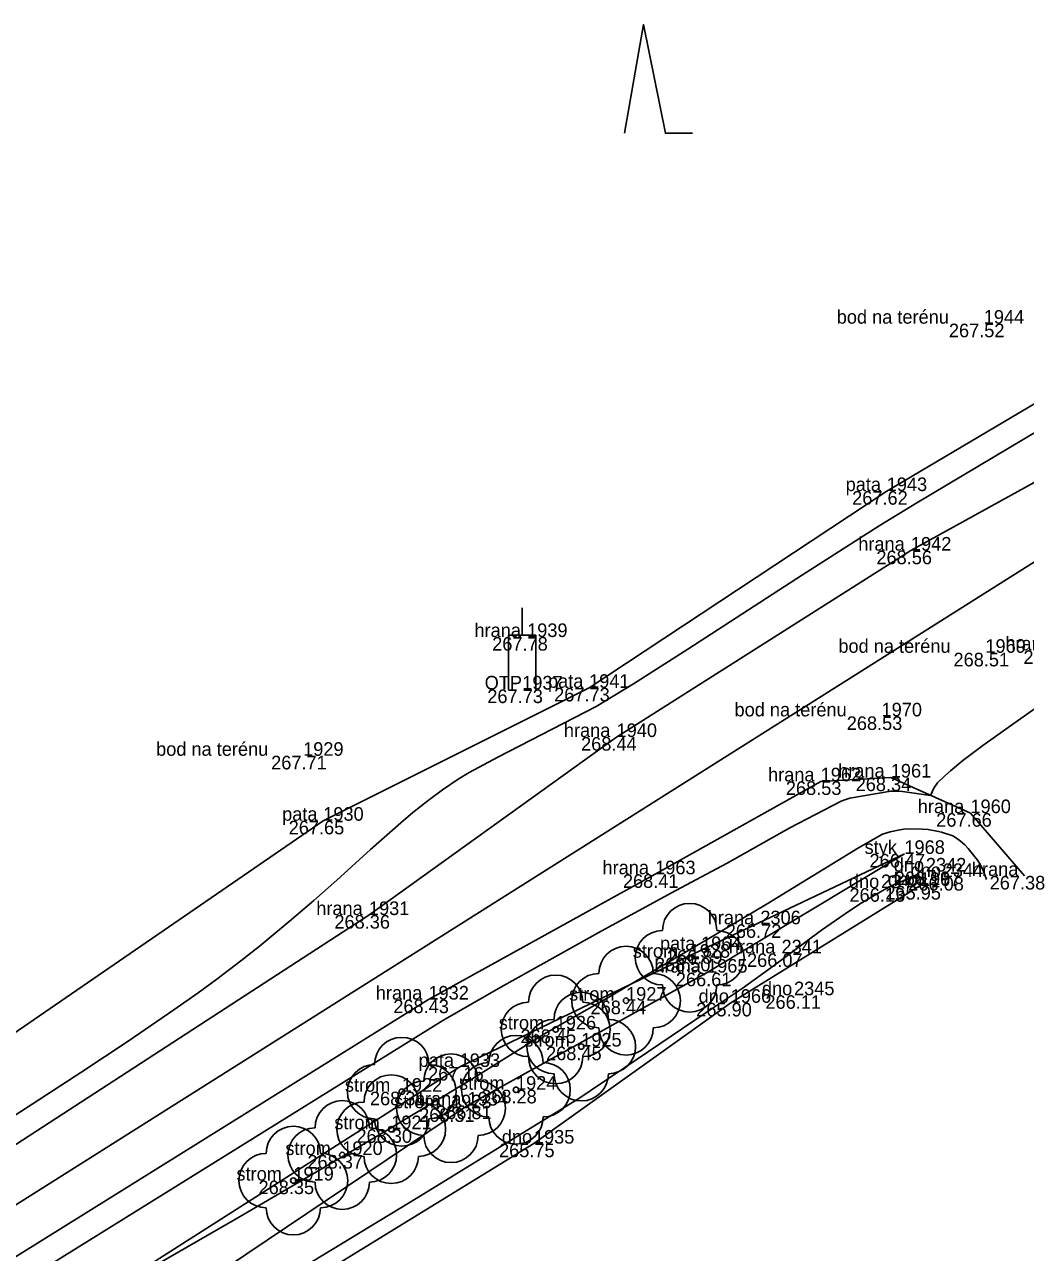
# Model space of a CAD drawing. Extents: x -567962 to -566460, y -1093720 to -1089838.
# Drawn here: x -566722.99 to -566686.17, y -1090086.58 to -1090041.4 of the extents above; entities that cross this region are included whole.
import ezdxf

# ---------------------------------------------------------------- set-up
doc = ezdxf.new("R2010")
doc.units = 0
for name, color, linetype in [('0_osa hráze', 7, 'Continuous'), ('bod_znacka', 7, 'Continuous'), ('cislo_bodu', 7, 'Continuous'), ('hrana_L', 7, 'Continuous'), ('hrana_P', 7, 'Continuous'), ('kod_bodu', 7, 'Continuous'), ('norm_vrst', 7, 'Continuous'), ('ostatni', 7, 'Continuous'), ('stromy', 7, 'Continuous'), ('Vrstva 1', 7, 'Continuous'), ('vyska_bodu', 7, 'Continuous')]:
    doc.layers.add(name, color=color, linetype=linetype)

# ---------------------------------------------------------------- blocks, each defined once
blk = doc.blocks.new('4.12')
at = {"layer": 'Vrstva 1'}
for points in [[(0, 0.2), (0, 0.3)], [(-0.05, 0), (-0.05, 0.2), (0.05, 0.2), (0.05, 0)]]:
    blk.add_lwpolyline(points, dxfattribs=at)
blk = doc.blocks.new('3.08')
at = {"layer": 'Vrstva 1'}
blk.add_lwpolyline([(-0.07, 0), (0, 0.4), (0.08, 0), (0.18, 0)], dxfattribs=at)

msp = doc.modelspace()

# ---------------------------------------------------------------- linework, layer by layer
at = {"layer": '0_osa hráze'}
msp.add_lwpolyline([(-566672.431, -1090052.714), (-566840.66, -1090158.92), (-566848.661, -1090164.285)], dxfattribs=at)
at = {"layer": 'bod_znacka'}
for p, q in [((-566687.7, -1090052.41), (-566687.7, -1090052.41)), ((-566691.27, -1090058.57), (-566691.27, -1090058.57)), ((-566690.38, -1090060.76), (-566690.38, -1090060.76)), ((-566704.5, -1090063.94), (-566704.5, -1090063.94)), ((-566687.64, -1090064.52), (-566687.64, -1090064.52)), ((-566704.68, -1090065.87), (-566704.68, -1090065.87)), ((-566702.22, -1090065.81), (-566702.22, -1090065.81)), ((-566691.46, -1090066.86), (-566691.46, -1090066.86)), ((-566701.21, -1090067.62), (-566701.21, -1090067.62)), ((-566712.74, -1090068.31), (-566712.74, -1090068.31)), ((-566691.12, -1090069.11), (-566691.12, -1090069.11)), ((-566693.7, -1090069.25), (-566693.7, -1090069.25)), ((-566688.19, -1090070.42), (-566688.19, -1090070.42)), ((-566712, -1090070.7), (-566712, -1090070.7)), ((-566690.62, -1090071.92), (-566690.62, -1090071.92)), ((-566699.79, -1090072.67), (-566699.79, -1090072.67)), ((-566689.83, -1090072.57), (-566689.83, -1090072.57)), ((-566689.21, -1090072.77), (-566689.21, -1090072.77)), ((-566686.2, -1090072.73), (-566686.2, -1090072.73)), ((-566691.48, -1090073.18), (-566691.48, -1090073.18)), ((-566690.05, -1090073.1), (-566690.05, -1090073.1)), ((-566710.32, -1090074.17), (-566710.32, -1090074.17)), ((-566695.92, -1090074.51), (-566695.92, -1090074.51)), ((-566698.1, -1090075.46), (-566698.1, -1090075.46)), ((-566698.52, -1090075.74), (-566698.52, -1090075.74)), ((-566695.14, -1090075.58), (-566695.14, -1090075.58)), ((-566697.88, -1090076.29), (-566697.88, -1090076.29)), ((-566708.13, -1090077.28), (-566708.13, -1090077.28)), ((-566700.86, -1090077.32), (-566700.86, -1090077.32)), ((-566694.68, -1090077.12), (-566694.68, -1090077.12)), ((-566697.01, -1090077.4), (-566697.01, -1090077.4)), ((-566703.45, -1090078.38), (-566703.45, -1090078.38)), ((-566702.51, -1090079.01), (-566702.51, -1090079.01)), ((-566706.98, -1090079.76), (-566706.98, -1090079.76)), ((-566709.11, -1090080.67), (-566709.11, -1090080.67)), ((-566704.91, -1090080.6), (-566704.91, -1090080.6)), ((-566707.3, -1090081.28), (-566707.3, -1090081.28)), ((-566706.69, -1090081.18), (-566706.69, -1090081.18)), ((-566709.5, -1090082.05), (-566709.5, -1090082.05)), ((-566704.25, -1090082.58), (-566704.25, -1090082.58)), ((-566711.3, -1090083), (-566711.3, -1090083)), ((-566713.1, -1090083.94), (-566713.1, -1090083.94))]:
    msp.add_line(p, q, dxfattribs=at)
at = {"layer": 'hrana_L'}
for p, q in [((-566691.27, -1090058.57), (-566676.59, -1090049.88)), ((-566673.39, -1090051.38), (-566690.38, -1090060.76)), ((-566691.27, -1090058.57), (-566702.22, -1090065.81)), ((-566690.38, -1090060.76), (-566701.21, -1090067.62)), ((-566702.22, -1090065.81), (-566712, -1090070.7)), ((-566701.21, -1090067.62), (-566710.32, -1090074.17)), ((-566693.7, -1090069.25), (-566691.12, -1090069.11)), ((-566688.19, -1090070.42), (-566691.12, -1090069.11)), ((-566693.7, -1090069.25), (-566699.79, -1090072.67)), ((-566688.19, -1090070.42), (-566686.2, -1090072.73)), ((-566712, -1090070.7), (-566726.46, -1090080.64)), ((-566698.1, -1090075.46), (-566690.62, -1090071.92)), ((-566690.62, -1090071.92), (-566697.88, -1090076.29)), ((-566708.13, -1090077.28), (-566699.79, -1090072.67)), ((-566710.32, -1090074.17), (-566724.86, -1090083.62)), ((-566698.1, -1090075.46), (-566706.98, -1090079.76)), ((-566697.88, -1090076.29), (-566706.69, -1090081.18)), ((-566733.33, -1090092.97), (-566708.13, -1090077.28)), ((-566731.46, -1090095.36), (-566706.98, -1090079.76)), ((-566706.69, -1090081.18), (-566730.03, -1090096.85))]:
    msp.add_line(p, q, dxfattribs=at)
at = {"layer": 'hrana_P'}
for p, q in [((-566697.01, -1090077.4), (-566690.05, -1090073.1)), ((-566704.25, -1090082.58), (-566697.01, -1090077.4)), ((-566730.44, -1090098.63), (-566704.25, -1090082.58))]:
    msp.add_line(p, q, dxfattribs=at)
at = {"layer": 'norm_vrst'}
for points in [[(-566682.788, -1090054.611), (-566690.167, -1090059.001), (-566691.547, -1090059.844), (-566694.373, -1090061.647), (-566698.592, -1090064.385), (-566700.583, -1090065.657), (-566701.963, -1090066.501), (-566705.58, -1090068.356), (-566706.627, -1090068.929), (-566707.033, -1090069.176), (-566707.608, -1090069.559), (-566708.146, -1090069.959), (-566708.701, -1090070.399), (-566709.144, -1090070.772), (-566710.261, -1090071.764), (-566711.498, -1090072.889), (-566712.341, -1090073.635), (-566713.248, -1090074.413), (-566714.363, -1090075.329), (-566715.035, -1090075.858), (-566715.911, -1090076.526), (-566716.605, -1090077.03), (-566717.494, -1090077.657), (-566719.173, -1090078.806), (-566720.914, -1090079.966), (-566722.704, -1090081.135), (-566724.539, -1090082.312)], [(-566723.987, -1090088.226), (-566707.595, -1090078.051), (-566705.465, -1090076.826), (-566701.78, -1090074.758), (-566699.029, -1090073.272), (-566697.135, -1090072.255), (-566694.833, -1090070.96), (-566692.941, -1090069.978), (-566692.816, -1090069.929), (-566692.624, -1090069.875), (-566691.118, -1090069.617), (-566690.865, -1090069.616), (-566690.685, -1090069.63), (-566689.654, -1090069.766), (-566689.532, -1090069.502), (-566689.399, -1090069.308), (-566689.126, -1090069.045), (-566688.922, -1090068.862), (-566688.464, -1090068.489), (-566687.73, -1090067.937), (-566686.336, -1090066.933), (-566685.174, -1090066.118)], [(-566721.012, -1090088.702), (-566715.142, -1090085.31), (-566711.594, -1090083.235), (-566709.713, -1090082.124), (-566706.598, -1090080.247), (-566704.338, -1090078.834), (-566703.795, -1090078.505), (-566701.494, -1090077.194), (-566700.682, -1090076.71), (-566697.6, -1090074.907), (-566695.67, -1090073.757), (-566692.314, -1090071.691), (-566691.422, -1090071.199), (-566691.144, -1090071.11), (-566690.853, -1090071.045), (-566690.642, -1090071.016), (-566690.418, -1090070.998), (-566689.951, -1090071.01), (-566689.742, -1090071.027), (-566689.361, -1090071.094), (-566689.254, -1090071.119), (-566688.908, -1090071.231), (-566688.842, -1090071.261), (-566688.708, -1090071.343), (-566688.559, -1090071.451), (-566688.399, -1090071.592), (-566688.268, -1090071.726), (-566688.025, -1090072.022), (-566687.922, -1090072.168), (-566687.817, -1090072.34), (-566687.736, -1090072.489), (-566687.655, -1090072.695), (-566687.602, -1090072.865)], [(-566728.912, -1090096.881), (-566714.828, -1090088.392), (-566708.518, -1090084.561), (-566704.308, -1090081.98), (-566702.601, -1090080.917), (-566702.143, -1090080.618), (-566700.899, -1090079.785), (-566697.915, -1090077.752), (-566696.591, -1090076.868), (-566695.402, -1090076.02), (-566693.67, -1090074.732), (-566692.641, -1090074.015), (-566692.212, -1090073.735), (-566691.799, -1090073.485), (-566691.355, -1090073.233), (-566691.047, -1090073.073), (-566690.58, -1090072.877), (-566690.342, -1090072.795), (-566690.187, -1090072.757), (-566690.139, -1090072.758), (-566690.066, -1090072.778), (-566689.977, -1090072.819), (-566689.926, -1090072.871), (-566689.872, -1090073.083)]]:
    msp.add_lwpolyline(points, dxfattribs=at)
at = {"layer": 'stromy'}
for centre in [(-566698.52, -1090075.74), (-566700.86, -1090077.32), (-566703.45, -1090078.38), (-566702.51, -1090079.01), (-566704.91, -1090080.6), (-566709.11, -1090080.67), (-566707.3, -1090081.28), (-566709.5, -1090082.05), (-566711.3, -1090083), (-566713.1, -1090083.94)]:
    msp.add_circle(centre, 0.1, dxfattribs=at)
for centre, start, end in [((-566698.52, -1090074.74), 0, 180), ((-566699.52, -1090075.74), 90, 270), ((-566697.52, -1090075.74), 270, 90), ((-566700.86, -1090076.32), 0, 180), ((-566703.45, -1090077.38), 0, 180), ((-566701.86, -1090077.32), 90, 270), ((-566699.86, -1090077.32), 270, 90), ((-566698.52, -1090076.74), 180, 0), ((-566702.51, -1090078.01), 0, 180), ((-566704.45, -1090078.38), 90, 270), ((-566702.45, -1090078.38), 270, 90), ((-566703.51, -1090079.01), 90, 270), ((-566701.51, -1090079.01), 270, 90), ((-566709.11, -1090079.67), 0, 180), ((-566704.91, -1090079.6), 0, 180), ((-566700.86, -1090078.32), 180, 0), ((-566707.3, -1090080.28), 0, 180), ((-566705.91, -1090080.6), 90, 270), ((-566703.45, -1090079.38), 180, 0), ((-566703.91, -1090080.6), 270, 90), ((-566710.11, -1090080.67), 90, 270), ((-566709.5, -1090081.05), 0, 180), ((-566708.11, -1090080.67), 270, 90), ((-566702.51, -1090080.01), 180, 0), ((-566708.3, -1090081.28), 90, 270), ((-566706.3, -1090081.28), 270, 90), ((-566711.3, -1090082), 0, 180), ((-566710.5, -1090082.05), 90, 270), ((-566708.5, -1090082.05), 270, 90), ((-566709.11, -1090081.67), 180, 0), ((-566704.91, -1090081.6), 180, 0), ((-566713.1, -1090082.94), 0, 180), ((-566712.3, -1090083), 90, 270), ((-566710.3, -1090083), 270, 90), ((-566707.3, -1090082.28), 180, 0), ((-566714.1, -1090083.94), 90, 270), ((-566712.1, -1090083.94), 270, 90), ((-566709.5, -1090083.05), 180, 0), ((-566711.3, -1090084), 180, 0), ((-566713.1, -1090084.94), 180, 0)]:
    msp.add_arc(centre, 1, start, end, dxfattribs=at)

# ---------------------------------------------------------------- block references
at = {"layer": 'ostatni', "xscale": 10, "yscale": 10}
for name, p in [('3.08', (-566700.213, -1090045.403)), ('4.12', (-566704.68, -1090065.87))]:
    msp.add_blockref(name, p, dxfattribs=at)

# ---------------------------------------------------------------- texts
at = {"layer": 'cislo_bodu'}
for s, p in [('1944', (-566687.7, -1090052.41)), ('1943', (-566691.27, -1090058.57)), ('1942', (-566690.38, -1090060.76)), ('1939', (-566704.5, -1090063.94)), ('1969', (-566687.64, -1090064.52)), ('1937', (-566704.68, -1090065.87)), ('1941', (-566702.22, -1090065.81)), ('1970', (-566691.46, -1090066.86)), ('1940', (-566701.21, -1090067.62)), ('1929', (-566712.74, -1090068.31)), ('1962', (-566693.7, -1090069.25)), ('1961', (-566691.12, -1090069.11)), ('1960', (-566688.19, -1090070.42)), ('1930', (-566712, -1090070.7)), ('1968', (-566690.62, -1090071.92)), ('1963', (-566699.79, -1090072.67)), ('2342', (-566689.83, -1090072.57)), ('2344', (-566689.21, -1090072.77)), ('2343', (-566691.48, -1090073.18)), ('1967', (-566690.05, -1090073.1)), ('1931', (-566710.32, -1090074.17)), ('2306', (-566695.92, -1090074.51)), ('1964', (-566698.1, -1090075.46)), ('2341', (-566695.14, -1090075.58)), ('1928', (-566698.52, -1090075.74)), ('1965', (-566697.88, -1090076.29)), ('1932', (-566708.13, -1090077.28)), ('1927', (-566700.86, -1090077.32)), ('1966', (-566697.01, -1090077.4)), ('2345', (-566694.68, -1090077.12)), ('1926', (-566703.45, -1090078.38)), ('1925', (-566702.51, -1090079.01)), ('1933', (-566706.98, -1090079.76)), ('1922', (-566709.11, -1090080.67)), ('1924', (-566704.91, -1090080.6)), ('1923', (-566707.3, -1090081.28)), ('1934', (-566706.69, -1090081.18)), ('1921', (-566709.5, -1090082.05)), ('1935', (-566704.25, -1090082.58)), ('1920', (-566711.3, -1090083)), ('1919', (-566713.1, -1090083.94))]:
    msp.add_text(s, height=0.5, dxfattribs=at).set_placement(p)
at = {"layer": 'kod_bodu'}
for s, p in [('bod na terénu', (-566693.109, -1090052.41)), ('pata', (-566692.782, -1090058.57)), ('hrana', (-566692.317, -1090060.76)), ('hrana', (-566706.437, -1090063.94)), ('bod na terénu', (-566693.049, -1090064.52)), ('hrana', (-566686.907, -1090064.43)), ('OTP', (-566706.062, -1090065.87)), ('pata', (-566703.732, -1090065.81)), ('bod na terénu', (-566696.869, -1090066.86)), ('hrana', (-566703.147, -1090067.62)), ('bod na terénu', (-566718.149, -1090068.31)), ('hrana', (-566695.637, -1090069.25)), ('hrana', (-566693.057, -1090069.11)), ('hrana', (-566690.127, -1090070.42)), ('pata', (-566713.512, -1090070.7)), ('styk', (-566692.084, -1090071.92)), ('hrana', (-566701.727, -1090072.67)), ('dno', (-566691.011, -1090072.57)), ('dno', (-566690.391, -1090072.77)), ('hrana', (-566688.137, -1090072.73)), ('dno', (-566692.661, -1090073.18)), ('dno', (-566691.231, -1090073.1)), ('hrana', (-566712.257, -1090074.17)), ('hrana', (-566697.857, -1090074.51)), ('pata', (-566699.612, -1090075.46)), ('hrana', (-566697.077, -1090075.58)), ('strom', (-566700.614, -1090075.74)), ('hrana', (-566699.817, -1090076.29)), ('hrana', (-566710.067, -1090077.28)), ('strom', (-566702.954, -1090077.32)), ('dno', (-566698.191, -1090077.4)), ('dno', (-566695.861, -1090077.12)), ('strom', (-566705.544, -1090078.38)), ('strom', (-566704.604, -1090079.01)), ('pata', (-566708.492, -1090079.76)), ('strom', (-566711.204, -1090080.67)), ('strom', (-566707.004, -1090080.6)), ('strom', (-566709.394, -1090081.28)), ('hrana', (-566708.627, -1090081.18)), ('strom', (-566711.594, -1090082.05)), ('dno', (-566705.431, -1090082.58)), ('strom', (-566713.394, -1090083)), ('strom', (-566715.194, -1090083.94))]:
    msp.add_text(s, height=0.5, dxfattribs=at).set_placement(p)
at = {"layer": 'vyska_bodu'}
for s, p in [('267.52', (-566688.983, -1090052.91)), ('267.62', (-566692.542, -1090059.07)), ('268.56', (-566691.65, -1090061.26)), ('267.78', (-566705.785, -1090064.44)), ('268.51', (-566688.813, -1090065.02)), ('268.29', (-566686.24, -1090064.93)), ('267.73', (-566705.965, -1090066.37)), ('267.73', (-566703.505, -1090066.31)), ('268.53', (-566692.741, -1090067.36)), ('268.44', (-566702.515, -1090068.12)), ('267.71', (-566713.917, -1090068.81)), ('268.34', (-566692.413, -1090069.61)), ('268.53', (-566694.981, -1090069.75)), ('267.66', (-566689.45, -1090070.92)), ('267.65', (-566713.272, -1090071.2)), ('266.47', (-566691.903, -1090072.42)), ('268.41', (-566700.975, -1090073.17)), ('266.19', (-566690.98, -1090073.07)), ('266.08', (-566690.478, -1090073.27)), ('267.38', (-566687.483, -1090073.23)), ('266.13', (-566692.641, -1090073.68)), ('265.95', (-566691.32, -1090073.6)), ('268.36', (-566711.59, -1090074.67)), ('266.72', (-566697.192, -1090075.01)), ('266.89', (-566699.358, -1090075.96)), ('268.50', (-566699.799, -1090076.24)), ('266.07', (-566696.41, -1090076.08)), ('266.61', (-566699.029, -1090076.79)), ('268.43', (-566709.423, -1090077.78)), ('268.44', (-566702.165, -1090077.82)), ('266.11', (-566695.733, -1090077.62)), ('265.90', (-566698.278, -1090077.9)), ('268.45', (-566704.743, -1090078.88)), ('268.45', (-566703.803, -1090079.51)), ('267.16', (-566708.143, -1090080.26)), ('268.31', (-566710.283, -1090081.17)), ('268.28', (-566706.191, -1090081.1)), ('268.31', (-566708.473, -1090081.78)), ('266.81', (-566707.851, -1090081.68)), ('268.30', (-566710.779, -1090082.55)), ('265.75', (-566705.533, -1090083.08)), ('268.37', (-566712.583, -1090083.5)), ('268.35', (-566714.381, -1090084.44))]:
    msp.add_text(s, height=0.5, dxfattribs=at).set_placement(p)

doc.saveas('drawing.dxf')
